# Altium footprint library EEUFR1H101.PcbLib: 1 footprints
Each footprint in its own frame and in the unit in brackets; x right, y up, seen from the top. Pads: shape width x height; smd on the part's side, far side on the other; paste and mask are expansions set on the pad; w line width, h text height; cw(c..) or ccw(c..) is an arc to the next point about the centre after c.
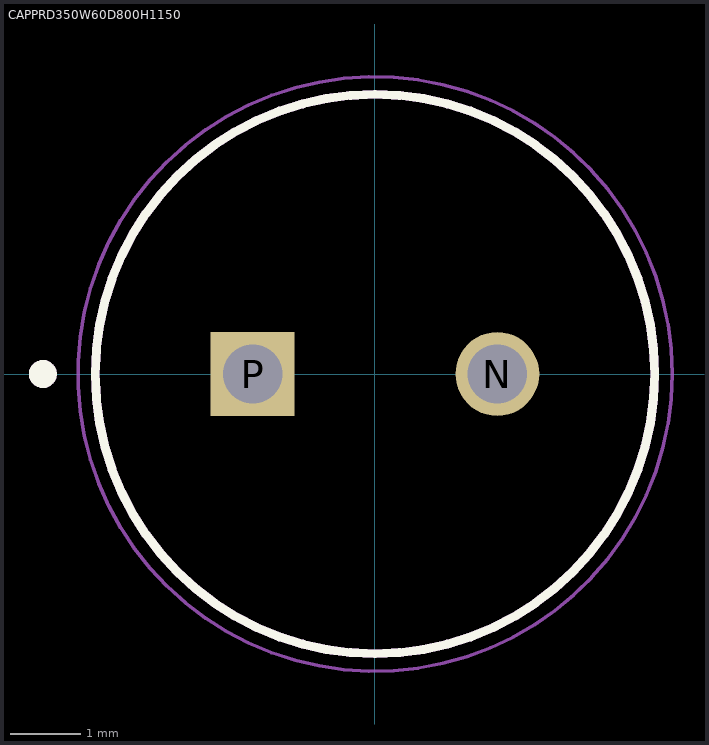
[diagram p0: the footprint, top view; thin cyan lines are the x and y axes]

## CAPPRD350W60D800H1150 [mm]
pads (2):
  round 1.2 hole 0.85: N(1.75,0)
  rect 1.2x1.2 hole 0.85: P(-1.75,0)
Top Overlay:
  circle w0.2: c-4.75,0 r0.1
  circle w0.127: c0,0 r4
Mechanical 13:
  circle w0.2: c-4.75,0 r0.1
  circle w0.127: c0,0 r4
Mechanical 15:
  circle w0.05: c0,0 r4.25
3D body "step_temp.STEP": height 11.5, standoff -17, extent -4,-4 4,4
